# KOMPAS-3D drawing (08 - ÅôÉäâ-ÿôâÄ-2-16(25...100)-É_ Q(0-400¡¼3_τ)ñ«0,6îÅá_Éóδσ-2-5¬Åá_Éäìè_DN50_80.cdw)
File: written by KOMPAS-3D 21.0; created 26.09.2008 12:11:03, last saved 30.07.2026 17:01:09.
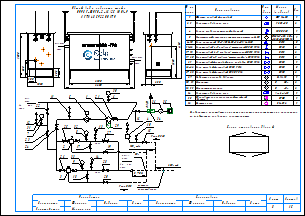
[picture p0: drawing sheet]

Sheets 1-2: A3, landscape

Document properties: Наименование: Макро:21; Автор: RaskoAdmin; Форматы листов документа: 2xA3; Полное имя файла: \\UR38nt01\Departments\КТО\КБ ПУРДГ\Заявки\Прайс-лист на типовые шкафы ГРПШ\ПУРДГ_стандарт_30_04_2026\ПУРДГ с РДНК\ПУРДГ-ШУГО-2-16(25...100)-Р_ Q(0-400нм3_ч)до0,6МПа_Рвых-2-5кПа_РДНК_DN50_80.cdw

Title block, sheet 1: Наименование: Пункт учета газа / ПУГ-Ш-400-Р / ЛГТИ.485922.001ТУ; designation: ЛГТИ.03.4411141; sheet number: 1; Количество листов документа: 2; organisation: ООО "ЭЛЬСТЕР Газэлектроника"; Форматы листов документа: A3; stored path: C:\Рабочие документы\Компас\ПУГ\Схема.cdw; Разработал: Устинов; Проверил: Кошкин; Утвердил: Кошкин
Title block, sheet 2: sheet number: 2; stored path: D:\Рабочие документы\Заявки\ПУРДГ\ПУРДГ-ШУЭО-2-100-Р 4411220.cdw; designation, second copy: ЛГТИ.03.4411141-

Views: Вид 1, Вид 2
Referenced files: wcvoit.frw
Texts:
  Normal
  Общий вид и габариты шкафа
  ПУРДГ-ШУГО-2-16(25...100)-Р
  DN80
  Выход газа
  DN50
  Вход газа
  logo-rasko-ge.png
  DN 1
  местное
  сопротивление
  Римп DN15
  Римп DN20
  Выход
  газа
  Р=     кПа
  Вход
  Р=       МПа
  PDI
  DN20
  № на
  схеме
  Усл.
  обозн.
  Марка
  (модель)
  Кол.
  Фильтр газовый фланцевый
  ФГ 16-50
  Регулятор давления газа
  РДНК-50
  Клапан предохранительный сбросной
  КПС DN20
  Измерительный комплекс с ротационным счетчиком Ду50
  СГ-ЭК-Р-(0,2...2,0)-
  Кран кнопочный VE-РАСКО-НЗ-1,6-G1/2-М20
  DN15
  Кран шаровой "под приварку" штуцерный DN20 PN16
  Кран шаровой "под приварку" штуцерный DN15 PN16
  Кран шаровой "под приварку" штуцерный п/п DN15 PN16
  Кран шаровой фланцевый с мех. приводом DN50 PN16
  Кран шаровой фланцевый DN50 PN16
  Кран шаровой фланцевый DN80 PN16
  Индикатор перепада давления
  Манометр
  Манометр-напоромер
  Обогреватель газогорелочный шкафной
  (Эльтон")
  Счетчик газа
  Delta 15
  0...     МПа
  0...     кПа
  Venio-A-15
  ОГШН
  BK-G1,6
  Схема открывания дверей
  Предприятие изготовитель может заменять комплектующие на аналогичные,
  не ухудшающие заявленных характеристик.
  Должность
  Конструктор
  Фамилия
  Подпись
  Дата
  Согласовано
  Максимкин
  Лист
  Листов
  POLYLINE_STYLE_0.18_RGB_0_0_0
  POLYLINE_STYLE_0.50_RGB_0_0_0
  POLYLINE_STYLE_0.34_RGB_0_0_0
  PHANTOM_RGB_0_0_0_SC_1_THICK_0.18
  K5LT_THIN_RGB_0_0_0_THICK_0.18
  K5LT32769_RGB_0_0_0_THICK_0.18
  K5LT12_RGB_0_0_0_SC_1_THICK_0.18
  K5LT_DASHED_RGB_0_0_0_SC_1_THICK_0.18
  ACISOTGL_RGB_0_0_0_SC_0.8_THICK_0.25
  CONTINUOUS_RGB_0_127_31_THICK_0.3
  CONTINUOUS_RGB_0_0_255_THICK_0.35
  CONTINUOUS_RGB_255_0_0_THICK_0.35
  POLYLINE_STYLE_0.25_RGB_0_0_0
  CONTINUOUS_RGB_0_0_0_THICK_0.5
  POLYLINE_STYLE_0.35_RGB_0_0_255
  CONTINUOUS_RGB_0_0_0_THICK_0.4
  CONTINUOUS_RGB_0_0_0_THICK_0.35
  НЕВИДИМАЯ_RGB_0_0_0_SC_0.3_THICK_0.25
  СONTINUOUS_RGB_0_0_0_THICK_0.25
  ОСЕВАЯ2_RGB_248_153_30_SC_0.3_THICK_0.25
  Без оформления
Dimensions and other numbers on the sheet: 1; 1500; 250; 300; 1050; 550; 305; 2300; 4130; 2000; 2600; 5,,,7DN 1; 7; 31; 12; 22; 23; 24; 11; 5; 21; 6; 30; 25; 32; 8; 2; 17; 13; 27; 19; 4; 10; 15; 26; 33; 9; 3; 18; 14; 28; 20; 29; 16; 34; 35; 36; 2, 3; 6-10; 11-16; 17, 18; 19, 20; 22-26; 27, 28; 30, 31; 32, 33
